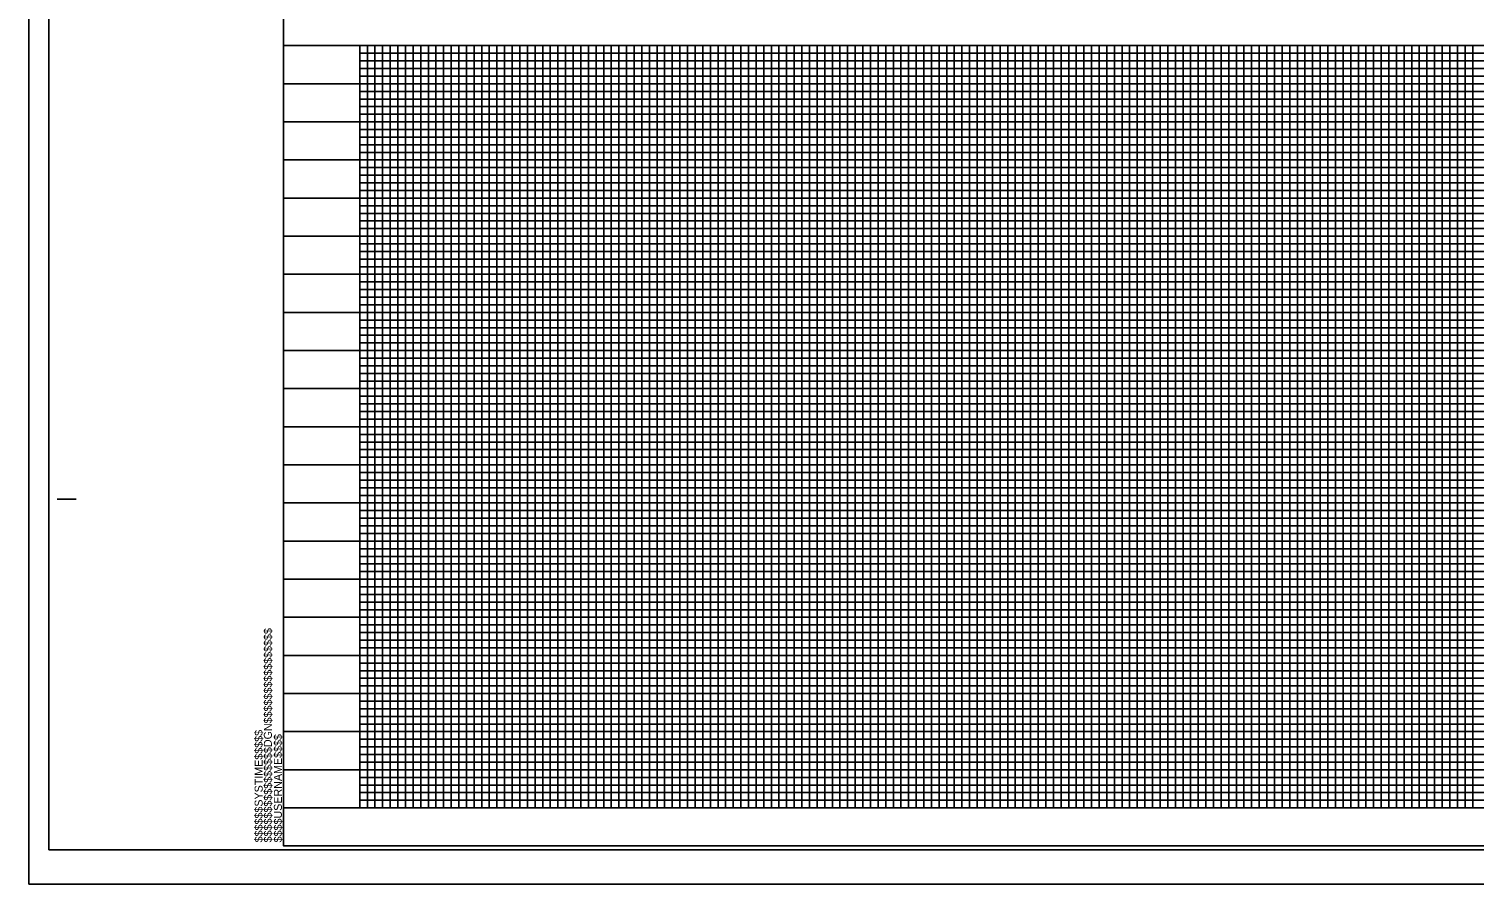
# Model space of a CAD drawing. Extents: x 2327371 to 2329279, y 159556 to 160656.
# Drawn here: x 2327371 to 2328319, y 159556 to 160117 of the extents above; entities that cross this region are included whole.
import ezdxf

# ---------------------------------------------------------------- set-up
doc = ezdxf.new("R2010")
doc.units = 0
for name, color, linetype in [('Scratch_Level_0', 7, 'Continuous'), ('Sheet Cutting Line CELL', 7, 'Continuous'), ('Sheet DOT Grid CELL', 7, 'Continuous'), ('Sheet Layout Profile Border Port 2', 7, 'Continuous'), ('Sheet Plot Border Inside CELL', 7, 'Continuous'), ('Sheet Plot Border Outside CELL', 7, 'Continuous'), ('Sheet Profile CELL', 7, 'Continuous'), ('Sheet Profile Grid Major CELL', 7, 'Continuous'), ('Sheet Profile Grid Middle CELL', 7, 'Continuous'), ('Sheet Profile Grid Minor CELL', 7, 'Continuous')]:
    doc.layers.add(name, color=color, linetype=linetype)

msp = doc.modelspace()

# ---------------------------------------------------------------- linework, layer by layer
at = {"layer": 'Scratch_Level_0'}
msp.add_lwpolyline([(2327587.98, 159606.31), (2327587.98, 160106.31), (2328987.98, 160106.31), (2328987.98, 159606.31)], close=True, dxfattribs=at)
at = {"layer": 'Sheet Cutting Line CELL'}
for p, q in [((2327370.98, 160656.31), (2327370.98, 159556.31)), ((2327370.98, 159556.31), (2329054.98, 159556.31))]:
    msp.add_line(p, q, dxfattribs=at)
at = {"layer": 'Sheet DOT Grid CELL'}
for p, q in [((2327537.98, 160106.31), (2329037.87, 160106.31)), ((2327587.98, 160106.31), (2327587.98, 159606.31)), ((2327637.98, 160106.31), (2327637.98, 159606.31)), ((2327687.98, 160106.31), (2327687.98, 159606.31)), ((2327737.98, 160106.31), (2327737.98, 159606.31)), ((2327787.98, 160106.31), (2327787.98, 159606.31)), ((2327837.98, 160106.31), (2327837.98, 159606.31)), ((2327887.98, 160106.31), (2327887.98, 159606.31)), ((2327937.98, 160106.31), (2327937.98, 159606.31)), ((2327987.98, 160106.31), (2327987.98, 159606.31)), ((2328037.98, 160106.31), (2328037.98, 159606.31)), ((2328087.98, 160106.31), (2328087.98, 159606.31)), ((2328137.98, 160106.31), (2328137.98, 159606.31)), ((2328187.98, 160106.31), (2328187.98, 159606.31)), ((2328237.98, 160106.31), (2328237.98, 159606.31)), ((2328287.98, 160106.31), (2328287.98, 159606.31)), ((2327537.98, 160056.31), (2329037.87, 160056.31)), ((2327537.98, 160006.31), (2329037.87, 160006.31)), ((2327537.98, 159956.31), (2329037.87, 159956.31)), ((2327537.98, 159906.31), (2329037.87, 159906.31)), ((2327537.98, 159856.31), (2329037.87, 159856.31)), ((2327537.98, 159806.31), (2329037.87, 159806.31)), ((2327537.98, 159756.31), (2329037.87, 159756.31)), ((2327537.98, 159706.31), (2329037.87, 159706.31)), ((2327537.98, 159656.31), (2329037.87, 159656.31))]:
    msp.add_line(p, q, dxfattribs=at)
at = {"layer": 'Sheet Layout Profile Border Port 2'}
msp.add_lwpolyline([(2327587.98, 160106.31), (2328987.98, 160106.31), (2328987.98, 159606.31), (2327587.98, 159606.31)], close=True, dxfattribs=at)
at = {"layer": 'Sheet Plot Border Inside CELL'}
msp.add_lwpolyline([(2327383.98, 159578.76), (2329050.48, 159578.76), (2329050.48, 160633.86), (2327383.98, 160633.86)], close=True, dxfattribs=at)
at = {"layer": 'Sheet Plot Border Outside CELL'}
msp.add_lwpolyline([(2327370.98, 159556.31), (2329054.98, 159556.31), (2329054.98, 160656.31), (2327370.98, 160656.31)], close=True, dxfattribs=at)
at = {"layer": 'Sheet Profile CELL'}
for p, q in [((2327537.98, 160106.31), (2329037.98, 160106.31)), ((2327389.48, 159808.81), (2327401.98, 159808.81)), ((2329037.98, 159606.31), (2327537.98, 159606.31)), ((2327537.98, 159581.31), (2329037.98, 159581.31)), ((2327537.98, 159581.31), (2327537.98, 159581.31)), ((2327537.98, 159581.31), (2327537.98, 159581.31)), ((2327537.98, 159581.31), (2327537.98, 159581.31)), ((2327537.98, 159581.31), (2327537.98, 159581.31)), ((2327537.98, 159581.31), (2327537.98, 159581.31)), ((2327537.98, 159581.31), (2327537.98, 159581.31)), ((2327537.98, 159581.31), (2327537.98, 159581.31))]:
    msp.add_line(p, q, dxfattribs=at)
msp.add_lwpolyline([(2329037.98, 160631.31), (2327537.98, 160631.31), (2327537.98, 159581.31), (2329037.98, 159581.31)], close=True, dxfattribs=at)
msp.add_lwpolyline([(2327575.48, 159581.31), (2327575.48, 159581.31)], dxfattribs=at)
at = {"layer": 'Sheet Profile Grid Major CELL'}
for p, q in [((2328037.98, 160106.31), (2328087.98, 160106.31)), ((2328137.98, 160106.31), (2328187.98, 160106.31)), ((2328237.98, 160106.31), (2328287.98, 160106.31)), ((2327537.98, 159606.31), (2327537.98, 159606.31))]:
    msp.add_line(p, q, dxfattribs=at)
for points in [[(2327587.98, 160106.31), (2327587.98, 159606.31), (2327637.98, 159606.31), (2327637.98, 160106.31), (2327687.98, 160106.31), (2327687.98, 159606.31), (2327737.98, 159606.31), (2327737.98, 160106.31), (2327787.98, 160106.31), (2327787.98, 159606.31), (2327837.98, 159606.31), (2327837.98, 160106.31), (2327887.98, 160106.31), (2327887.98, 159606.31), (2327937.98, 159606.31), (2327937.98, 160106.31), (2327987.98, 160106.31), (2327987.98, 159606.31), (2328037.98, 159606.31), (2328037.98, 160106.31), (2328087.98, 160106.31), (2328087.98, 159606.31), (2328137.98, 159606.31), (2328137.98, 160106.31), (2328187.98, 160106.31), (2328187.98, 159606.31), (2328237.98, 159606.31), (2328237.98, 160106.31), (2328287.98, 160106.31), (2328287.98, 159606.31), (2328337.98, 159606.31)], [(2329037.98, 160056.31), (2327537.98, 160056.31)], [(2329037.98, 160006.31), (2327537.98, 160006.31), (2327537.98, 159956.31), (2329037.98, 159956.31)], [(2329037.98, 159906.31), (2327537.98, 159906.31), (2327537.98, 159856.31), (2329037.98, 159856.31)], [(2329037.98, 159806.31), (2327537.98, 159806.31), (2327537.98, 159756.31), (2329037.98, 159756.31)], [(2329037.98, 159706.31), (2327537.98, 159706.31), (2327537.98, 159706.31), (2327537.98, 159656.31), (2329037.98, 159656.31)], [(2329037.98, 159606.31), (2327537.98, 159606.31)]]:
    msp.add_lwpolyline(points, dxfattribs=at)
at = {"layer": 'Sheet Profile Grid Middle CELL'}
for points in [[(2327562.98, 160106.31), (2327612.98, 160106.31), (2327612.98, 159606.31), (2327662.98, 159606.31), (2327662.98, 160106.31), (2327712.98, 160106.31), (2327712.98, 159606.31), (2327762.98, 159606.31), (2327762.98, 160106.31), (2327812.98, 160106.31), (2327812.98, 159606.31), (2327862.98, 159606.31), (2327862.98, 160106.31), (2327912.98, 160106.31), (2327912.98, 159606.31), (2327962.98, 159606.31), (2327962.98, 160106.31), (2328012.98, 160106.31), (2328012.98, 159606.31), (2328062.98, 159606.31), (2328062.98, 160106.31), (2328112.98, 160106.31), (2328112.98, 159606.31), (2328162.98, 159606.31), (2328162.98, 159606.31), (2328162.98, 160106.31), (2328212.98, 160106.31), (2328212.98, 159606.31), (2328262.98, 159606.31), (2328262.98, 160106.31), (2328312.98, 160106.31), (2328312.98, 159606.31), (2328362.98, 159606.31)], [(2327537.98, 160081.31), (2329037.98, 160081.31)], [(2329037.98, 160031.31), (2327537.98, 160031.31), (2327537.98, 159981.31), (2329037.98, 159981.31)], [(2329037.98, 159931.31), (2327537.98, 159931.31), (2327537.98, 159881.31), (2329037.98, 159881.31)], [(2329037.98, 159831.31), (2327537.98, 159831.31), (2327537.98, 159781.31), (2329037.98, 159781.31)], [(2329037.98, 159731.31), (2327537.98, 159731.31), (2327537.98, 159681.31), (2329037.98, 159681.31)], [(2329037.98, 159631.31), (2327537.98, 159631.31)]]:
    msp.add_lwpolyline(points, dxfattribs=at)
at = {"layer": 'Sheet Profile Grid Minor CELL'}
for p, q in [((2327587.98, 160101.31), (2328987.98, 160101.31)), ((2328987.98, 160096.31), (2327587.98, 160096.31)), ((2327587.98, 160091.31), (2328987.98, 160091.31)), ((2328987.98, 160086.31), (2327587.98, 160086.31)), ((2327587.98, 160076.31), (2328987.98, 160076.31)), ((2328987.98, 160071.31), (2327587.98, 160071.31)), ((2327587.98, 160066.31), (2328987.98, 160066.31)), ((2328987.98, 160061.31), (2327587.98, 160061.31)), ((2327587.98, 160051.31), (2328987.98, 160051.31)), ((2328987.98, 160046.31), (2327587.98, 160046.31)), ((2327587.98, 160041.31), (2328987.98, 160041.31)), ((2328987.98, 160036.31), (2327587.98, 160036.31)), ((2327587.98, 160026.31), (2328987.98, 160026.31)), ((2328987.98, 160021.31), (2327587.98, 160021.31)), ((2327587.98, 160016.31), (2328987.98, 160016.31)), ((2328987.98, 160011.31), (2327587.98, 160011.31)), ((2327587.98, 160001.31), (2328987.98, 160001.31)), ((2328987.98, 159996.31), (2327587.98, 159996.31)), ((2327587.98, 159991.31), (2328987.98, 159991.31)), ((2328987.98, 159986.31), (2327587.98, 159986.31)), ((2327587.98, 159976.31), (2328987.98, 159976.31)), ((2328987.98, 159971.31), (2327587.98, 159971.31)), ((2327587.98, 159966.31), (2328987.98, 159966.31)), ((2328987.98, 159961.31), (2327587.98, 159961.31)), ((2327587.98, 159951.31), (2328987.98, 159951.31)), ((2328987.98, 159946.31), (2327587.98, 159946.31)), ((2327587.98, 159941.31), (2328987.98, 159941.31)), ((2328987.98, 159936.31), (2327587.98, 159936.31)), ((2327587.98, 159926.31), (2328987.98, 159926.31)), ((2328987.98, 159921.31), (2327587.98, 159921.31)), ((2327587.98, 159916.31), (2328987.98, 159916.31)), ((2328987.98, 159911.31), (2327587.98, 159911.46)), ((2327587.98, 159901.31), (2328987.98, 159901.31)), ((2328987.98, 159896.31), (2327587.98, 159896.31)), ((2327587.98, 159891.31), (2328987.98, 159891.31)), ((2328987.98, 159886.31), (2327587.98, 159886.31)), ((2327587.98, 159876.31), (2328987.98, 159876.31)), ((2328987.98, 159871.31), (2327587.98, 159871.31)), ((2327587.98, 159866.31), (2328987.98, 159866.31)), ((2328987.98, 159861.31), (2327587.98, 159861.31)), ((2327587.98, 159851.31), (2328987.98, 159851.31)), ((2328987.98, 159846.31), (2327587.98, 159846.31)), ((2327587.98, 159841.31), (2328987.98, 159841.31)), ((2328987.98, 159836.31), (2327587.98, 159836.31)), ((2327587.98, 159826.31), (2328987.98, 159826.31)), ((2328987.98, 159821.31), (2327587.98, 159821.31)), ((2327587.98, 159816.31), (2328987.98, 159816.31)), ((2328987.98, 159811.31), (2327587.98, 159811.31)), ((2327587.98, 159801.31), (2328987.98, 159801.31)), ((2328987.98, 159796.31), (2327587.98, 159796.31)), ((2327587.98, 159791.31), (2328987.98, 159791.31)), ((2328987.98, 159786.31), (2327587.98, 159786.31)), ((2327587.98, 159776.31), (2328987.98, 159776.31)), ((2328987.98, 159771.31), (2327587.98, 159771.31)), ((2327587.98, 159766.31), (2328987.98, 159766.31)), ((2328987.98, 159761.31), (2327587.98, 159761.31)), ((2327587.98, 159751.31), (2328987.98, 159751.31)), ((2328987.98, 159746.31), (2327587.98, 159746.31)), ((2327587.98, 159741.31), (2328987.98, 159741.31)), ((2328987.98, 159736.31), (2327587.98, 159736.31)), ((2327587.98, 159726.31), (2328987.98, 159726.31)), ((2328987.98, 159721.31), (2327587.98, 159721.31)), ((2327587.98, 159716.31), (2328987.98, 159716.31)), ((2328987.98, 159711.31), (2327587.98, 159711.31)), ((2327587.98, 159701.31), (2328987.98, 159701.31)), ((2328987.98, 159696.31), (2327587.98, 159696.31)), ((2327587.98, 159691.31), (2328987.98, 159691.31)), ((2328987.98, 159686.31), (2327587.98, 159686.31)), ((2327587.98, 159676.31), (2328987.98, 159676.31)), ((2328987.98, 159671.31), (2327587.98, 159671.31)), ((2327587.98, 159666.31), (2328987.98, 159666.31)), ((2328987.98, 159661.31), (2327587.98, 159661.31)), ((2327587.98, 159651.31), (2328987.98, 159651.31)), ((2328987.98, 159646.31), (2327587.98, 159646.31)), ((2327587.98, 159641.31), (2328987.98, 159641.31)), ((2328987.98, 159636.31), (2327587.98, 159636.31)), ((2327587.98, 159626.31), (2328987.98, 159626.31)), ((2328987.98, 159621.31), (2327587.98, 159621.31)), ((2327587.98, 159616.31), (2328987.98, 159616.31)), ((2327587.98, 159611.31), (2328987.98, 159611.31))]:
    msp.add_line(p, q, dxfattribs=at)
for points in [[(2327587.98, 160106.31), (2327592.98, 160106.31), (2327592.98, 159606.31), (2327597.98, 159606.31), (2327597.98, 160106.31), (2327602.98, 160106.31), (2327602.98, 159606.31), (2327607.98, 159606.31), (2327607.98, 160106.31), (2327617.98, 160106.31), (2327617.98, 159606.31), (2327622.98, 159606.31), (2327622.98, 160106.31), (2327627.98, 160106.31), (2327627.98, 159606.31), (2327632.98, 159606.31), (2327642.98, 159606.31), (2327647.98, 159606.31), (2327647.98, 160106.31), (2327652.98, 160106.31), (2327652.98, 159606.31), (2327657.98, 159606.31), (2327657.98, 160106.31), (2327667.98, 160106.31), (2327667.98, 159606.31), (2327672.98, 159606.31), (2327672.98, 160106.31), (2327677.98, 160106.31), (2327677.98, 159606.31), (2327682.98, 159606.31), (2327682.98, 160106.31), (2327692.98, 160106.31), (2327692.98, 159606.31), (2327697.98, 159606.31), (2327697.98, 160106.31), (2327702.98, 160106.31), (2327702.98, 159606.31), (2327707.98, 159606.31), (2327707.98, 160106.31), (2327717.98, 160106.31), (2327717.98, 159606.31), (2327722.98, 159606.31), (2327722.98, 160106.31), (2327727.98, 160106.31), (2327727.98, 159606.31), (2327732.98, 159606.31), (2327732.98, 160106.31), (2327742.98, 160106.31), (2327742.98, 159606.31), (2327747.98, 159606.31), (2327747.98, 160106.31), (2327752.98, 160106.31), (2327752.98, 159606.31), (2327757.98, 159606.31), (2327757.98, 160106.31), (2327767.98, 160106.31), (2327767.98, 159606.31), (2327772.98, 159606.31), (2327772.98, 160106.31), (2327777.98, 160106.31), (2327777.98, 159606.31), (2327782.98, 159606.31), (2327782.98, 160106.31), (2327792.98, 160106.31), (2327792.98, 159606.31), (2327797.98, 159606.31), (2327797.98, 160106.31), (2327802.98, 160106.31), (2327802.98, 159606.31)], [(2327632.98, 159606.31), (2327632.98, 160106.31), (2327642.98, 160106.31), (2327642.98, 159606.31)], [(2327802.98, 159606.31), (2327807.98, 159606.31), (2327807.98, 160106.31), (2327817.98, 160106.31), (2327817.98, 159606.31), (2327822.98, 159606.31), (2327822.98, 160106.31), (2327827.98, 160106.31), (2327827.98, 159606.31), (2327832.98, 159606.31), (2327832.98, 160106.31), (2327842.98, 160106.31), (2327842.98, 159606.31), (2327847.98, 159606.31), (2327847.98, 160106.31), (2327852.98, 160106.31), (2327852.98, 159606.31), (2327857.98, 159606.31), (2327857.98, 160106.31), (2327867.98, 160106.31), (2327867.98, 159606.31), (2327872.98, 159606.31), (2327872.98, 160106.31), (2327877.98, 160106.31), (2327877.98, 159606.31), (2327882.98, 159606.31), (2327882.98, 160106.31), (2327892.98, 160106.31), (2327892.98, 159606.31), (2327897.98, 159606.31), (2327897.98, 160106.31), (2327902.98, 160106.31), (2327902.98, 159606.31), (2327907.98, 159606.31), (2327907.98, 160106.31), (2327917.98, 160106.31), (2327917.98, 159606.31), (2327922.98, 159606.31), (2327922.98, 160106.31), (2327927.98, 160106.31), (2327927.98, 159606.31), (2327932.98, 159606.31), (2327932.98, 160106.31), (2327942.98, 160106.31), (2327942.98, 159606.31), (2327947.98, 159606.31), (2327947.98, 160106.31), (2327952.98, 160106.31), (2327952.98, 159606.31), (2327957.98, 159606.31), (2327957.98, 160106.31), (2327967.98, 160106.31), (2327967.98, 159606.31), (2327972.98, 159606.31), (2327972.98, 160106.31), (2327977.98, 160106.31), (2327977.98, 159606.31), (2327982.98, 159606.31), (2327982.98, 160106.31), (2327992.98, 160106.31), (2327992.98, 159606.31), (2327997.98, 159606.31), (2327997.98, 160106.31), (2328002.98, 160106.31), (2328002.98, 159606.31), (2328007.98, 159606.31), (2328007.98, 160106.31), (2328017.98, 160106.31), (2328017.98, 159606.31), (2328022.98, 159606.31), (2328022.98, 160106.31), (2328027.98, 160106.31), (2328027.98, 159606.31), (2328032.98, 159606.31), (2328032.98, 160106.31), (2328042.98, 160106.31), (2328042.98, 159606.31), (2328047.98, 159606.31), (2328047.98, 160106.31), (2328052.98, 160106.31), (2328052.98, 159606.31), (2328057.98, 159606.31), (2328057.98, 160106.31), (2328067.98, 160106.31), (2328067.98, 159606.31), (2328072.98, 159606.31), (2328072.98, 160106.31), (2328077.98, 160106.31), (2328077.98, 159606.31), (2328082.98, 159606.31), (2328082.98, 160106.31), (2328092.98, 160106.31), (2328092.98, 159606.31), (2328097.98, 159606.31), (2328097.98, 160106.31), (2328102.98, 160106.31), (2328102.98, 159606.31), (2328107.98, 159606.31), (2328107.98, 160106.31), (2328117.98, 160106.31)], [(2328117.98, 160106.31), (2328117.98, 159606.31), (2328122.98, 159606.31), (2328122.98, 160106.31), (2328127.98, 160106.31), (2328127.98, 159606.31), (2328132.98, 159606.31), (2328132.98, 160106.31), (2328142.98, 160106.31), (2328142.98, 159606.31), (2328147.98, 159606.31), (2328147.98, 160106.31), (2328152.98, 160106.31), (2328152.98, 159606.31), (2328157.98, 159606.31), (2328157.98, 160106.31), (2328167.98, 160106.31), (2328167.98, 159606.31), (2328172.98, 159606.31), (2328172.98, 160106.31), (2328177.98, 160106.31), (2328177.98, 159606.31), (2328182.98, 159606.31), (2328182.98, 160106.31), (2328192.98, 160106.31), (2328192.98, 159606.31), (2328197.98, 159606.31), (2328197.98, 160106.31), (2328202.98, 160106.31), (2328202.98, 159606.31), (2328207.98, 159606.31), (2328207.98, 160106.31), (2328217.98, 160106.31), (2328217.98, 159606.31), (2328222.98, 159606.31), (2328222.98, 160106.31), (2328227.98, 160106.31), (2328227.98, 159606.31), (2328232.98, 159606.31), (2328232.98, 160106.31), (2328242.98, 160106.31), (2328242.98, 159606.31), (2328242.98, 159606.31), (2328247.98, 159606.31), (2328247.98, 160106.31), (2328252.98, 160106.31), (2328252.98, 159606.31), (2328257.98, 159606.31), (2328257.98, 160106.31), (2328267.98, 160106.31), (2328267.98, 159606.31), (2328272.98, 159606.31), (2328272.98, 160106.31), (2328277.98, 160106.31), (2328277.98, 159606.31), (2328282.98, 159606.31), (2328282.98, 160106.31), (2328292.98, 160106.31), (2328292.98, 159606.31), (2328297.98, 159606.31), (2328297.98, 160106.31), (2328302.98, 160106.31), (2328302.98, 159606.31), (2328307.98, 159606.31), (2328307.98, 160106.31), (2328317.98, 160106.31), (2328317.98, 159606.31), (2328322.98, 159606.31)]]:
    msp.add_lwpolyline(points, dxfattribs=at)

# ---------------------------------------------------------------- texts
at = {"layer": 'Sheet Profile CELL'}
for s, p in [('$$$$$$$$$$$$$$$$DGN$$$$$$$$$$$$$$$$', (2327530.34, 159583.68)), ('$$$$$$SYSTIME$$$$$', (2327524.29, 159583.68)), ('$$$$USERNAME$$$$', (2327536.92, 159583.69))]:
    msp.add_text(s, height=5.25, rotation=90, dxfattribs=at).set_placement(p)

doc.saveas('drawing.dxf')
